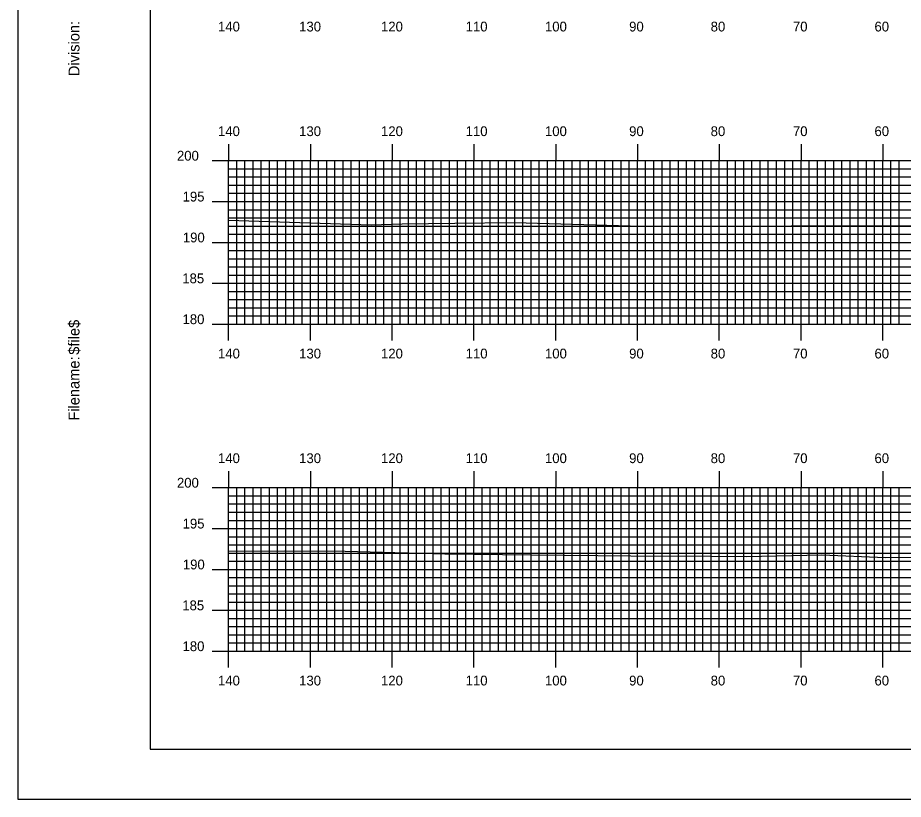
# Model space of a CAD drawing. Extents: x 1798781 to 1799124, y 442591 to 442811.
# Drawn here: x 1798781.2 to 1798889.5, y 442590.5 to 442686.2 of the extents above; entities that cross this region are included whole.
import ezdxf

# ---------------------------------------------------------------- set-up
doc = ezdxf.new("R2010")
doc.units = 0
for name, color, linetype in [('BORDER', 7, 'Continuous'), ('H_V ANNOTATION', 7, 'Continuous'), ('MAJOR', 7, 'Continuous'), ('MINOR', 7, 'Continuous'), ('PLOT BOUNDARY', 7, 'Continuous'), ('S_Roadway_Centerline', 7, 'Continuous')]:
    doc.layers.add(name, color=color, linetype=linetype)

msp = doc.modelspace()

# ---------------------------------------------------------------- linework, layer by layer
at = {"layer": 'BORDER'}
msp.add_lwpolyline([(1798797.38, 442596.67), (1799117.38, 442596.67), (1799117.38, 442806.67), (1798797.38, 442806.67)], close=True, dxfattribs=at)
at = {"layer": 'MAJOR'}
for p, q in [((1798806.98, 442670.67), (1798806.98, 442668.67)), ((1798816.98, 442670.67), (1798816.98, 442668.67)), ((1798826.98, 442670.67), (1798826.98, 442668.67)), ((1798836.98, 442670.67), (1798836.98, 442668.67)), ((1798846.98, 442670.67), (1798846.98, 442668.67)), ((1798856.98, 442670.67), (1798856.98, 442668.67)), ((1798866.98, 442670.67), (1798866.98, 442668.67)), ((1798876.98, 442670.67), (1798876.98, 442668.67)), ((1798886.98, 442670.67), (1798886.98, 442668.67)), ((1798804.98, 442668.67), (1798806.98, 442668.67)), ((1798806.98, 442668.67), (1799086.98, 442668.67)), ((1798806.98, 442648.67), (1798806.98, 442668.67)), ((1798806.98, 442648.67), (1798806.98, 442668.67)), ((1798806.98, 442668.67), (1799086.98, 442668.67)), ((1798816.98, 442648.67), (1798816.98, 442668.67)), ((1798826.98, 442648.67), (1798826.98, 442668.67)), ((1798836.98, 442648.67), (1798836.98, 442668.67)), ((1798846.98, 442648.67), (1798846.98, 442668.67)), ((1798856.98, 442648.67), (1798856.98, 442668.67)), ((1798866.98, 442648.67), (1798866.98, 442668.67)), ((1798876.98, 442648.67), (1798876.98, 442668.67)), ((1798886.98, 442648.67), (1798886.98, 442668.67)), ((1798804.98, 442663.67), (1798806.98, 442663.67)), ((1798806.98, 442663.67), (1799086.98, 442663.67)), ((1798804.98, 442658.67), (1798806.98, 442658.67)), ((1798806.98, 442658.67), (1799086.98, 442658.67)), ((1798804.98, 442653.67), (1798806.98, 442653.67)), ((1798806.98, 442653.67), (1799086.98, 442653.67)), ((1798804.98, 442648.67), (1798806.98, 442648.67)), ((1798806.98, 442648.67), (1799086.98, 442648.67)), ((1798806.98, 442648.67), (1799086.98, 442648.67)), ((1798806.98, 442646.66), (1798806.98, 442648.67)), ((1798816.98, 442646.66), (1798816.98, 442648.67)), ((1798826.98, 442646.66), (1798826.98, 442648.67)), ((1798836.98, 442646.66), (1798836.98, 442648.67)), ((1798846.98, 442646.66), (1798846.98, 442648.67)), ((1798856.98, 442646.66), (1798856.98, 442648.67)), ((1798866.98, 442646.66), (1798866.98, 442648.67)), ((1798876.98, 442646.66), (1798876.98, 442648.67)), ((1798886.98, 442646.66), (1798886.98, 442648.67)), ((1798806.98, 442630.67), (1798806.98, 442628.67)), ((1798816.98, 442630.67), (1798816.98, 442628.67)), ((1798826.98, 442630.67), (1798826.98, 442628.67)), ((1798836.98, 442630.67), (1798836.98, 442628.67)), ((1798846.98, 442630.67), (1798846.98, 442628.67)), ((1798856.98, 442630.67), (1798856.98, 442628.67)), ((1798866.98, 442630.67), (1798866.98, 442628.67)), ((1798876.98, 442630.67), (1798876.98, 442628.67)), ((1798886.98, 442630.67), (1798886.98, 442628.67)), ((1798804.98, 442628.67), (1798806.98, 442628.67)), ((1798806.98, 442628.67), (1799086.98, 442628.67)), ((1798806.98, 442608.67), (1798806.98, 442628.67)), ((1798806.98, 442608.67), (1798806.98, 442628.67)), ((1798806.98, 442628.67), (1799086.98, 442628.67)), ((1798816.98, 442608.67), (1798816.98, 442628.67)), ((1798826.98, 442608.67), (1798826.98, 442628.67)), ((1798836.98, 442608.67), (1798836.98, 442628.67)), ((1798846.98, 442608.67), (1798846.98, 442628.67)), ((1798856.98, 442608.67), (1798856.98, 442628.67)), ((1798866.98, 442608.67), (1798866.98, 442628.67)), ((1798876.98, 442608.67), (1798876.98, 442628.67)), ((1798886.98, 442608.67), (1798886.98, 442628.67)), ((1798804.98, 442623.67), (1798806.98, 442623.67)), ((1798806.98, 442623.67), (1799086.98, 442623.67)), ((1798804.98, 442618.67), (1798806.98, 442618.67)), ((1798806.98, 442618.67), (1799086.98, 442618.67)), ((1798804.98, 442613.67), (1798806.98, 442613.67)), ((1798806.98, 442613.67), (1799086.98, 442613.67)), ((1798804.98, 442608.67), (1798806.98, 442608.67)), ((1798806.98, 442608.67), (1799086.98, 442608.67)), ((1798806.98, 442608.67), (1799086.98, 442608.67)), ((1798806.98, 442606.66), (1798806.98, 442608.67)), ((1798816.98, 442606.66), (1798816.98, 442608.67)), ((1798826.98, 442606.66), (1798826.98, 442608.67)), ((1798836.98, 442606.66), (1798836.98, 442608.67)), ((1798846.98, 442606.66), (1798846.98, 442608.67)), ((1798856.98, 442606.66), (1798856.98, 442608.67)), ((1798866.98, 442606.66), (1798866.98, 442608.67)), ((1798876.98, 442606.66), (1798876.98, 442608.67)), ((1798886.98, 442606.66), (1798886.98, 442608.67))]:
    msp.add_line(p, q, dxfattribs=at)
at = {"layer": 'MINOR'}
for p, q in [((1798807.98, 442648.67), (1798807.98, 442668.67)), ((1798808.98, 442648.67), (1798808.98, 442668.67)), ((1798809.98, 442648.67), (1798809.98, 442668.67)), ((1798810.98, 442648.67), (1798810.98, 442668.67)), ((1798811.98, 442648.67), (1798811.98, 442668.67)), ((1798812.98, 442648.67), (1798812.98, 442668.67)), ((1798813.98, 442648.67), (1798813.98, 442668.67)), ((1798814.98, 442648.67), (1798814.98, 442668.67)), ((1798815.98, 442648.67), (1798815.98, 442668.67)), ((1798817.98, 442648.67), (1798817.98, 442668.67)), ((1798818.98, 442648.67), (1798818.98, 442668.67)), ((1798819.98, 442648.67), (1798819.98, 442668.67)), ((1798820.98, 442648.67), (1798820.98, 442668.67)), ((1798821.98, 442648.67), (1798821.98, 442668.67)), ((1798822.98, 442648.67), (1798822.98, 442668.67)), ((1798823.98, 442648.67), (1798823.98, 442668.67)), ((1798824.98, 442648.67), (1798824.98, 442668.67)), ((1798825.98, 442648.67), (1798825.98, 442668.67)), ((1798827.98, 442648.67), (1798827.98, 442668.67)), ((1798828.98, 442648.67), (1798828.98, 442668.67)), ((1798829.98, 442648.67), (1798829.98, 442668.67)), ((1798830.98, 442648.67), (1798830.98, 442668.67)), ((1798831.98, 442648.67), (1798831.98, 442668.67)), ((1798832.98, 442648.67), (1798832.98, 442668.67)), ((1798833.98, 442648.67), (1798833.98, 442668.67)), ((1798834.98, 442648.67), (1798834.98, 442668.67)), ((1798835.98, 442648.67), (1798835.98, 442668.67)), ((1798837.98, 442648.67), (1798837.98, 442668.67)), ((1798838.98, 442648.67), (1798838.98, 442668.67)), ((1798839.98, 442648.67), (1798839.98, 442668.67)), ((1798840.98, 442648.67), (1798840.98, 442668.67)), ((1798841.98, 442648.67), (1798841.98, 442668.67)), ((1798842.98, 442648.67), (1798842.98, 442668.67)), ((1798843.98, 442648.67), (1798843.98, 442668.67)), ((1798844.98, 442648.67), (1798844.98, 442668.67)), ((1798845.98, 442648.67), (1798845.98, 442668.67)), ((1798847.98, 442648.67), (1798847.98, 442668.67)), ((1798848.98, 442648.67), (1798848.98, 442668.67)), ((1798849.98, 442648.67), (1798849.98, 442668.67)), ((1798850.98, 442648.67), (1798850.98, 442668.67)), ((1798851.98, 442648.67), (1798851.98, 442668.67)), ((1798852.98, 442648.67), (1798852.98, 442668.67)), ((1798853.98, 442648.67), (1798853.98, 442668.67)), ((1798854.98, 442648.67), (1798854.98, 442668.67)), ((1798855.98, 442648.67), (1798855.98, 442668.67)), ((1798857.98, 442648.67), (1798857.98, 442668.67)), ((1798858.98, 442648.67), (1798858.98, 442668.67)), ((1798859.98, 442648.67), (1798859.98, 442668.67)), ((1798860.98, 442648.67), (1798860.98, 442668.67)), ((1798861.98, 442648.67), (1798861.98, 442668.67)), ((1798862.98, 442648.67), (1798862.98, 442668.67)), ((1798863.98, 442648.67), (1798863.98, 442668.67)), ((1798864.98, 442648.67), (1798864.98, 442668.67)), ((1798865.98, 442648.67), (1798865.98, 442668.67)), ((1798867.98, 442648.67), (1798867.98, 442668.67)), ((1798868.98, 442648.67), (1798868.98, 442668.67)), ((1798869.98, 442648.67), (1798869.98, 442668.67)), ((1798870.98, 442648.67), (1798870.98, 442668.67)), ((1798871.98, 442648.67), (1798871.98, 442668.67)), ((1798872.98, 442648.67), (1798872.98, 442668.67)), ((1798873.98, 442648.67), (1798873.98, 442668.67)), ((1798874.98, 442648.67), (1798874.98, 442668.67)), ((1798875.98, 442648.67), (1798875.98, 442668.67)), ((1798877.98, 442648.67), (1798877.98, 442668.67)), ((1798878.98, 442648.67), (1798878.98, 442668.67)), ((1798879.98, 442648.67), (1798879.98, 442668.67)), ((1798880.98, 442648.67), (1798880.98, 442668.67)), ((1798881.98, 442648.67), (1798881.98, 442668.67)), ((1798882.98, 442648.67), (1798882.98, 442668.67)), ((1798883.98, 442648.67), (1798883.98, 442668.67)), ((1798884.98, 442648.67), (1798884.98, 442668.67)), ((1798885.98, 442648.67), (1798885.98, 442668.67)), ((1798887.98, 442648.67), (1798887.98, 442668.67)), ((1798888.98, 442648.67), (1798888.98, 442668.67)), ((1798806.98, 442667.67), (1799086.98, 442667.67)), ((1798806.98, 442667.67), (1798808.99, 442667.67)), ((1798806.98, 442666.67), (1799086.98, 442666.67)), ((1798806.98, 442666.67), (1798808.99, 442666.67)), ((1798806.98, 442665.67), (1799086.98, 442665.67)), ((1798806.98, 442665.67), (1798808.99, 442665.67)), ((1798806.98, 442664.67), (1799086.98, 442664.67)), ((1798806.98, 442664.67), (1798808.99, 442664.67)), ((1798806.98, 442662.67), (1799086.98, 442662.67)), ((1798806.98, 442662.67), (1798808.99, 442662.67)), ((1798806.98, 442661.67), (1799086.98, 442661.67)), ((1798806.98, 442661.67), (1798808.99, 442661.67)), ((1798806.98, 442660.67), (1799086.98, 442660.67)), ((1798806.98, 442660.67), (1798808.99, 442660.67)), ((1798806.98, 442659.67), (1799086.98, 442659.67)), ((1798806.98, 442659.67), (1798808.99, 442659.67)), ((1798806.98, 442657.67), (1799086.98, 442657.67)), ((1798806.98, 442657.67), (1798808.99, 442657.67)), ((1798806.98, 442656.67), (1799086.98, 442656.67)), ((1798806.98, 442656.67), (1798808.99, 442656.67)), ((1798806.98, 442655.67), (1799086.98, 442655.67)), ((1798806.98, 442655.67), (1798808.99, 442655.67)), ((1798806.98, 442654.67), (1799086.98, 442654.67)), ((1798806.98, 442654.67), (1798808.99, 442654.67)), ((1798806.98, 442652.67), (1799086.98, 442652.67)), ((1798806.98, 442652.67), (1798808.99, 442652.67)), ((1798806.98, 442651.67), (1799086.98, 442651.67)), ((1798806.98, 442651.67), (1798808.99, 442651.67)), ((1798806.98, 442650.67), (1799086.98, 442650.67)), ((1798806.98, 442650.67), (1798808.99, 442650.67)), ((1798806.98, 442649.67), (1799086.98, 442649.67)), ((1798806.98, 442649.67), (1798808.99, 442649.67)), ((1798807.98, 442608.67), (1798807.98, 442628.67)), ((1798808.98, 442608.67), (1798808.98, 442628.67)), ((1798809.98, 442608.67), (1798809.98, 442628.67)), ((1798810.98, 442608.67), (1798810.98, 442628.67)), ((1798811.98, 442608.67), (1798811.98, 442628.67)), ((1798812.98, 442608.67), (1798812.98, 442628.67)), ((1798813.98, 442608.67), (1798813.98, 442628.67)), ((1798814.98, 442608.67), (1798814.98, 442628.67)), ((1798815.98, 442608.67), (1798815.98, 442628.67)), ((1798817.98, 442608.67), (1798817.98, 442628.67)), ((1798818.98, 442608.67), (1798818.98, 442628.67)), ((1798819.98, 442608.67), (1798819.98, 442628.67)), ((1798820.98, 442608.67), (1798820.98, 442628.67)), ((1798821.98, 442608.67), (1798821.98, 442628.67)), ((1798822.98, 442608.67), (1798822.98, 442628.67)), ((1798823.98, 442608.67), (1798823.98, 442628.67)), ((1798824.98, 442608.67), (1798824.98, 442628.67)), ((1798825.98, 442608.67), (1798825.98, 442628.67)), ((1798827.98, 442608.67), (1798827.98, 442628.67)), ((1798828.98, 442608.67), (1798828.98, 442628.67)), ((1798829.98, 442608.67), (1798829.98, 442628.67)), ((1798830.98, 442608.67), (1798830.98, 442628.67)), ((1798831.98, 442608.67), (1798831.98, 442628.67)), ((1798832.98, 442608.67), (1798832.98, 442628.67)), ((1798833.98, 442608.67), (1798833.98, 442628.67)), ((1798834.98, 442608.67), (1798834.98, 442628.67)), ((1798835.98, 442608.67), (1798835.98, 442628.67)), ((1798837.98, 442608.67), (1798837.98, 442628.67)), ((1798838.98, 442608.67), (1798838.98, 442628.67)), ((1798839.98, 442608.67), (1798839.98, 442628.67)), ((1798840.98, 442608.67), (1798840.98, 442628.67)), ((1798841.98, 442608.67), (1798841.98, 442628.67)), ((1798842.98, 442608.67), (1798842.98, 442628.67)), ((1798843.98, 442608.67), (1798843.98, 442628.67)), ((1798844.98, 442608.67), (1798844.98, 442628.67)), ((1798845.98, 442608.67), (1798845.98, 442628.67)), ((1798847.98, 442608.67), (1798847.98, 442628.67)), ((1798848.98, 442608.67), (1798848.98, 442628.67)), ((1798849.98, 442608.67), (1798849.98, 442628.67)), ((1798850.98, 442608.67), (1798850.98, 442628.67)), ((1798851.98, 442608.67), (1798851.98, 442628.67)), ((1798852.98, 442608.67), (1798852.98, 442628.67)), ((1798853.98, 442608.67), (1798853.98, 442628.67)), ((1798854.98, 442608.67), (1798854.98, 442628.67)), ((1798855.98, 442608.67), (1798855.98, 442628.67)), ((1798857.98, 442608.67), (1798857.98, 442628.67)), ((1798858.98, 442608.67), (1798858.98, 442628.67)), ((1798859.98, 442608.67), (1798859.98, 442628.67)), ((1798860.98, 442608.67), (1798860.98, 442628.67)), ((1798861.98, 442608.67), (1798861.98, 442628.67)), ((1798862.98, 442608.67), (1798862.98, 442628.67)), ((1798863.98, 442608.67), (1798863.98, 442628.67)), ((1798864.98, 442608.67), (1798864.98, 442628.67)), ((1798865.98, 442608.67), (1798865.98, 442628.67)), ((1798867.98, 442608.67), (1798867.98, 442628.67)), ((1798868.98, 442608.67), (1798868.98, 442628.67)), ((1798869.98, 442608.67), (1798869.98, 442628.67)), ((1798870.98, 442608.67), (1798870.98, 442628.67)), ((1798871.98, 442608.67), (1798871.98, 442628.67)), ((1798872.98, 442608.67), (1798872.98, 442628.67)), ((1798873.98, 442608.67), (1798873.98, 442628.67)), ((1798874.98, 442608.67), (1798874.98, 442628.67)), ((1798875.98, 442608.67), (1798875.98, 442628.67)), ((1798877.98, 442608.67), (1798877.98, 442628.67)), ((1798878.98, 442608.67), (1798878.98, 442628.67)), ((1798879.98, 442608.67), (1798879.98, 442628.67)), ((1798880.98, 442608.67), (1798880.98, 442628.67)), ((1798881.98, 442608.67), (1798881.98, 442628.67)), ((1798882.98, 442608.67), (1798882.98, 442628.67)), ((1798883.98, 442608.67), (1798883.98, 442628.67)), ((1798884.98, 442608.67), (1798884.98, 442628.67)), ((1798885.98, 442608.67), (1798885.98, 442628.67)), ((1798887.98, 442608.67), (1798887.98, 442628.67)), ((1798888.98, 442608.67), (1798888.98, 442628.67)), ((1798806.98, 442627.67), (1799086.98, 442627.67)), ((1798806.98, 442627.67), (1798808.99, 442627.67)), ((1798806.98, 442626.67), (1799086.98, 442626.67)), ((1798806.98, 442626.67), (1798808.99, 442626.67)), ((1798806.98, 442625.67), (1799086.98, 442625.67)), ((1798806.98, 442625.67), (1798808.99, 442625.67)), ((1798806.98, 442624.67), (1799086.98, 442624.67)), ((1798806.98, 442624.67), (1798808.99, 442624.67)), ((1798806.98, 442622.67), (1799086.98, 442622.67)), ((1798806.98, 442622.67), (1798808.99, 442622.67)), ((1798806.98, 442621.67), (1799086.98, 442621.67)), ((1798806.98, 442621.67), (1798808.99, 442621.67)), ((1798806.98, 442620.67), (1799086.98, 442620.67)), ((1798806.98, 442620.67), (1798808.99, 442620.67)), ((1798806.98, 442619.67), (1799086.98, 442619.67)), ((1798806.98, 442619.67), (1798808.99, 442619.67)), ((1798806.98, 442617.67), (1799086.98, 442617.67)), ((1798806.98, 442617.67), (1798808.99, 442617.67)), ((1798806.98, 442616.67), (1799086.98, 442616.67)), ((1798806.98, 442616.67), (1798808.99, 442616.67)), ((1798806.98, 442615.67), (1799086.98, 442615.67)), ((1798806.98, 442615.67), (1798808.99, 442615.67)), ((1798806.98, 442614.67), (1799086.98, 442614.67)), ((1798806.98, 442614.67), (1798808.99, 442614.67)), ((1798806.98, 442612.67), (1799086.98, 442612.67)), ((1798806.98, 442612.67), (1798808.99, 442612.67)), ((1798806.98, 442611.67), (1799086.98, 442611.67)), ((1798806.98, 442611.67), (1798808.99, 442611.67)), ((1798806.98, 442610.67), (1799086.98, 442610.67)), ((1798806.98, 442610.67), (1798808.99, 442610.67)), ((1798806.98, 442609.67), (1799086.98, 442609.67)), ((1798806.98, 442609.67), (1798808.99, 442609.67))]:
    msp.add_line(p, q, dxfattribs=at)
at = {"layer": 'PLOT BOUNDARY'}
msp.add_lwpolyline([(1798781.2, 442590.55), (1799121.2, 442590.55), (1799121.2, 442810.55), (1798781.2, 442810.55)], close=True, dxfattribs=at)
at = {"layer": 'S_Roadway_Centerline'}
for points in [[(1798806.98, 442661.39), (1798824.41, 442660.82), (1798828.21, 442660.93), (1798834.63, 442661.03), (1798841.93, 442661.09), (1798858.9, 442660.63), (1798863.81, 442660.67), (1798875.78, 442660.69), (1798887.66, 442660.71), (1798899, 442660.71), (1798908.96, 442660.54), (1798923.75, 442660.38), (1798928.12, 442660.29), (1798931.41, 442660.32), (1798938.79, 442660.33), (1798953.83, 442660.48), (1798963.35, 442660.3), (1798972.99, 442660.16), (1798973.93, 442660.15), (1798974.6, 442660.14), (1798997.33, 442660.14), (1798997.39, 442660.14), (1798997.44, 442660.14), (1798998.09, 442660.14)], [(1798806.98, 442620.89), (1798813.86, 442620.92), (1798821.24, 442620.89), (1798833.44, 442620.56), (1798844.01, 442620.45), (1798856.16, 442620.31), (1798865.92, 442620.29), (1798870.32, 442620.25), (1798879.54, 442620.45), (1798887.31, 442620.11), (1798890.51, 442620.15), (1798893.93, 442620.12), (1798910.05, 442620.13), (1798915, 442620.06), (1798935.26, 442620.01), (1798942.91, 442619.97), (1798954.49, 442619.94), (1798960.78, 442619.98), (1798967.61, 442619.95), (1798972.46, 442619.97), (1798976.89, 442619.74), (1798992.58, 442619.51), (1798996.49, 442619.54), (1799015.91, 442619.74)]]:
    msp.add_lwpolyline(points, dxfattribs=at)

# ---------------------------------------------------------------- texts
at = {"layer": 'BORDER'}
for s, p in [('Division:', (1798788.75, 442679)), ('$file$', (1798788.75, 442644.92)), ('Filename:', (1798788.75, 442636.86))]:
    msp.add_text(s, height=1.339, rotation=90, dxfattribs=at).set_placement(p)
at = {"layer": 'H_V ANNOTATION'}
for s, p in [('140', (1798805.69, 442684.47)), ('130', (1798815.61, 442684.47)), ('120', (1798825.62, 442684.47)), ('110', (1798835.97, 442684.47)), ('100', (1798845.67, 442684.47)), ('90', (1798855.96, 442684.47)), ('80', (1798865.93, 442684.47)), ('70', (1798875.99, 442684.47)), ('60', (1798885.96, 442684.47)), ('140', (1798805.69, 442671.67)), ('130', (1798815.61, 442671.67)), ('120', (1798825.62, 442671.67)), ('110', (1798835.97, 442671.67)), ('100', (1798845.67, 442671.67)), ('90', (1798855.96, 442671.67)), ('80', (1798865.93, 442671.67)), ('70', (1798875.99, 442671.67)), ('60', (1798885.96, 442671.67)), ('200', (1798800.67, 442668.67)), ('195', (1798801.36, 442663.67)), ('190', (1798801.39, 442658.67)), ('185', (1798801.32, 442653.67)), ('180', (1798801.35, 442648.67)), ('140', (1798805.69, 442644.47)), ('130', (1798815.61, 442644.47)), ('120', (1798825.62, 442644.47)), ('110', (1798835.97, 442644.47)), ('100', (1798845.67, 442644.47)), ('90', (1798855.96, 442644.47)), ('80', (1798865.93, 442644.47)), ('70', (1798875.99, 442644.47)), ('60', (1798885.96, 442644.47)), ('140', (1798805.69, 442631.67)), ('130', (1798815.61, 442631.67)), ('120', (1798825.62, 442631.67)), ('110', (1798835.97, 442631.67)), ('100', (1798845.67, 442631.67)), ('90', (1798855.96, 442631.67)), ('80', (1798865.93, 442631.67)), ('70', (1798875.99, 442631.67)), ('60', (1798885.96, 442631.67)), ('200', (1798800.67, 442628.67)), ('195', (1798801.36, 442623.67)), ('190', (1798801.39, 442618.67)), ('185', (1798801.32, 442613.67)), ('180', (1798801.35, 442608.67)), ('140', (1798805.69, 442604.47)), ('130', (1798815.61, 442604.47)), ('120', (1798825.62, 442604.47)), ('110', (1798835.97, 442604.47)), ('100', (1798845.67, 442604.47)), ('90', (1798855.96, 442604.47)), ('80', (1798865.93, 442604.47)), ('70', (1798875.99, 442604.47)), ('60', (1798885.96, 442604.47))]:
    msp.add_text(s, height=1.2, dxfattribs=at).set_placement(p)
at = {"layer": 'MAJOR'}
for p in [(1798806.97, 442648.67), (1798806.97, 442608.67)]:
    msp.add_text('-', height=0.012, dxfattribs=at).set_placement(p)

doc.saveas('drawing.dxf')
